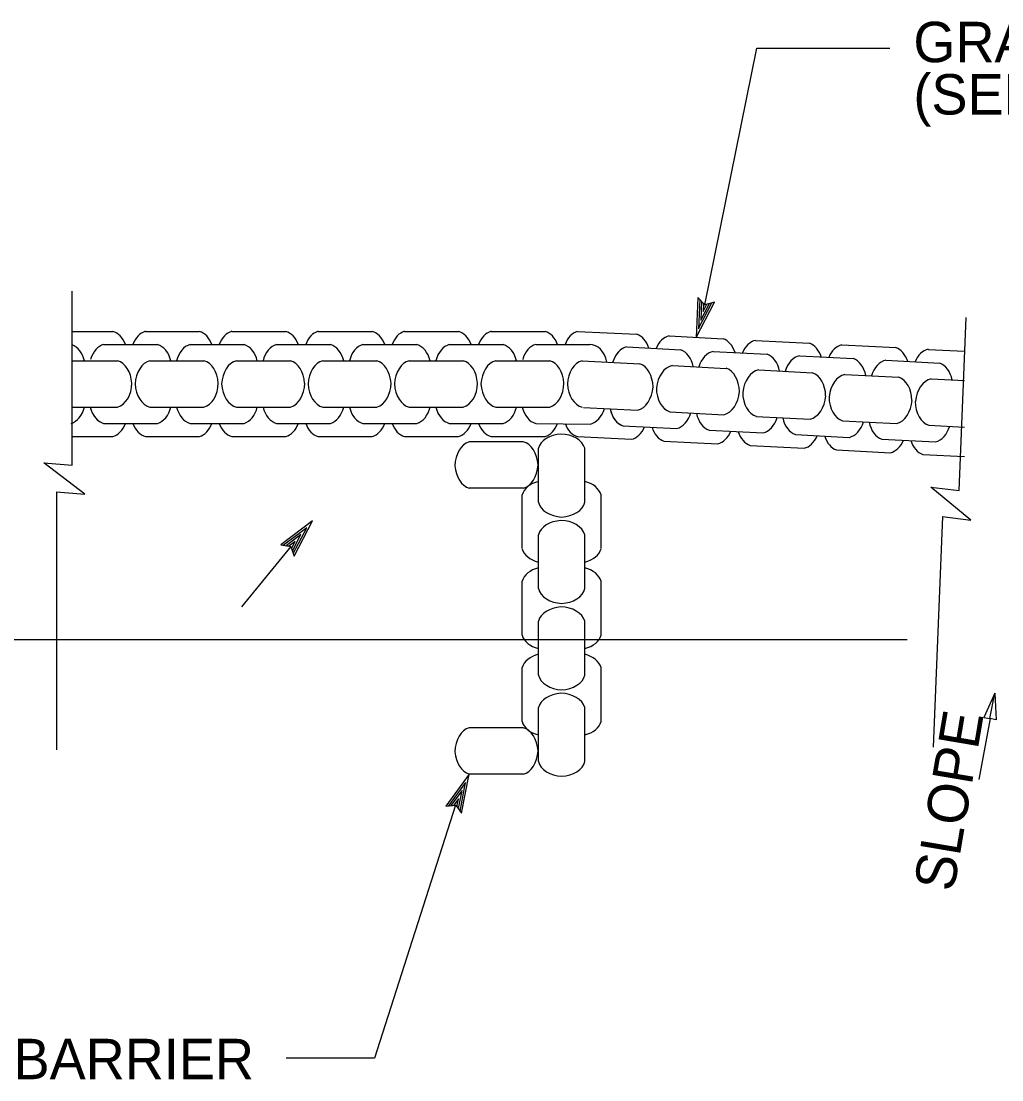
# Model space of a CAD drawing. Extents: x 6707406 to 6714471, y 1868570 to 1872341.
# Drawn here: x 6712657.6 to 6712803, y 1870285.3 to 1870442.4 of the extents above; entities that cross this region are included whole.
import ezdxf

# ---------------------------------------------------------------- set-up
doc = ezdxf.new("R2010")
doc.units = 0
for name, color, linetype in [('56 Stg 3 Anno', 7, 'Continuous'), ('C - SANDBAG', 7, 'Continuous'), ('G-SYMB', 7, 'Continuous'), ('G-TEXT', 7, 'Continuous')]:
    doc.layers.add(name, color=color, linetype=linetype)

msp = doc.modelspace()

# ---------------------------------------------------------------- linework, layer by layer
at = {"layer": '56 Stg 3 Anno'}
for p, q in [((6712757.94, 1870401.35), (6712757.69, 1870395.45)), ((6712757.69, 1870395.45), (6712760.42, 1870400.68)), ((6712758.98, 1870400.27), (6712757.94, 1870401.35)), ((6712757.94, 1870401.35), (6712757.94, 1870401.35)), ((6712758.22, 1870401.06), (6712758.03, 1870396.73)), ((6712758.04, 1870396.74), (6712760.02, 1870400.55)), ((6712758.49, 1870400.75), (6712758.37, 1870398.01)), ((6712758.37, 1870398.01), (6712759.66, 1870400.47)), ((6712758.77, 1870400.5), (6712758.72, 1870399.29)), ((6712758.72, 1870399.29), (6712759.27, 1870400.35)), ((6712760.42, 1870400.68), (6712758.98, 1870400.27)), ((6712760.42, 1870400.68), (6712760.42, 1870400.68)), ((6712757.69, 1870395.45), (6712757.69, 1870395.45)), ((6712700.78, 1870368.21), (6712696.07, 1870364.65)), ((6712699.91, 1870367.19), (6712696.48, 1870364.6)), ((6712697.9, 1870363.37), (6712699.92, 1870367.2)), ((6712698.03, 1870362.99), (6712700.78, 1870368.21)), ((6712700.78, 1870368.21), (6712700.78, 1870368.21)), ((6712699.06, 1870366.19), (6712696.85, 1870364.51)), ((6712697.78, 1870363.76), (6712699.06, 1870366.19)), ((6712696.07, 1870364.65), (6712696.07, 1870364.65)), ((6712696.07, 1870364.65), (6712697.54, 1870364.41)), ((6712698.2, 1870365.18), (6712697.26, 1870364.46)), ((6712697.54, 1870364.41), (6712698.03, 1870362.99)), ((6712697.64, 1870364.11), (6712698.2, 1870365.18)), ((6712698.03, 1870362.99), (6712698.03, 1870362.99)), ((6712724.02, 1870330.63), (6712720.53, 1870325.88)), ((6712723.48, 1870329.41), (6712720.94, 1870325.94)), ((6712722.65, 1870325.17), (6712723.49, 1870329.42)), ((6712722.88, 1870324.84), (6712724.02, 1870330.63)), ((6712724.02, 1870330.63), (6712724.02, 1870330.63)), ((6712722.95, 1870328.21), (6712721.31, 1870325.97)), ((6712722.42, 1870325.52), (6712722.95, 1870328.21)), ((6712720.53, 1870325.88), (6712722.01, 1870326.06)), ((6712722.42, 1870326.99), (6712721.72, 1870326.03)), ((6712722.01, 1870326.06), (6712722.88, 1870324.84)), ((6712722.18, 1870325.81), (6712722.42, 1870326.99)), ((6712720.53, 1870325.88), (6712720.53, 1870325.88)), ((6712722.88, 1870324.84), (6712722.88, 1870324.84))]:
    msp.add_line(p, q, dxfattribs=at)
at = {"layer": 'C - SANDBAG'}
for p, q in [((6712665.12, 1870396.34), (6712671.16, 1870396.34)), ((6712675.98, 1870396.34), (6712683.98, 1870396.34)), ((6712675.98, 1870396.34), (6712683.98, 1870396.34)), ((6712688.8, 1870396.34), (6712696.8, 1870396.34)), ((6712701.62, 1870396.34), (6712709.63, 1870396.34)), ((6712714.44, 1870396.34), (6712722.45, 1870396.34)), ((6712727.26, 1870396.34), (6712735.27, 1870396.34)), ((6712740.08, 1870396.34), (6712748.88, 1870395.9)), ((6712753.69, 1870395.66), (6712761.68, 1870395.24)), ((6712753.69, 1870395.66), (6712761.68, 1870395.24)), ((6712669.78, 1870394.39), (6712677.79, 1870394.39)), ((6712669.78, 1870394.39), (6712677.79, 1870394.39)), ((6712682.6, 1870394.39), (6712690.61, 1870394.39)), ((6712695.42, 1870394.39), (6712703.43, 1870394.39)), ((6712708.25, 1870394.39), (6712716.25, 1870394.39)), ((6712721.07, 1870394.39), (6712729.07, 1870394.39)), ((6712733.89, 1870394.38), (6712741.89, 1870394.38)), ((6712747.4, 1870394.02), (6712755.4, 1870393.61)), ((6712747.4, 1870394.02), (6712755.4, 1870393.61)), ((6712766.49, 1870394.99), (6712774.49, 1870394.58)), ((6712779.3, 1870394.33), (6712787.29, 1870393.92)), ((6712792.1, 1870393.67), (6712797.47, 1870393.4)), ((6712760.21, 1870393.36), (6712768.2, 1870392.95)), ((6712773.01, 1870392.7), (6712781.01, 1870392.29)), ((6712785.81, 1870392.04), (6712793.81, 1870391.63)), ((6712665.12, 1870391.98), (6712671.85, 1870391.98)), ((6712676.67, 1870391.98), (6712684.67, 1870391.98)), ((6712676.67, 1870391.98), (6712684.67, 1870391.98)), ((6712689.49, 1870391.98), (6712697.49, 1870391.98)), ((6712702.31, 1870391.98), (6712710.31, 1870391.98)), ((6712715.13, 1870391.98), (6712723.13, 1870391.98)), ((6712727.95, 1870391.98), (6712735.96, 1870391.98)), ((6712740.77, 1870391.98), (6712749.34, 1870391.52)), ((6712754.15, 1870391.27), (6712762.15, 1870390.85)), ((6712754.15, 1870391.27), (6712762.15, 1870390.85)), ((6712766.96, 1870390.61), (6712774.95, 1870390.19)), ((6712779.76, 1870389.95), (6712787.76, 1870389.53)), ((6712792.56, 1870389.28), (6712797.47, 1870389.03)), ((6712665.12, 1870385.09), (6712671.85, 1870385.09)), ((6712676.67, 1870385.09), (6712684.67, 1870385.09)), ((6712676.67, 1870385.09), (6712684.67, 1870385.09)), ((6712689.49, 1870385.09), (6712697.49, 1870385.09)), ((6712702.31, 1870385.09), (6712710.31, 1870385.09)), ((6712715.13, 1870385.09), (6712723.13, 1870385.09)), ((6712727.95, 1870385.09), (6712735.96, 1870385.09)), ((6712740.99, 1870385.05), (6712748.99, 1870384.63)), ((6712753.8, 1870384.39), (6712761.79, 1870383.97)), ((6712753.8, 1870384.39), (6712761.79, 1870383.97)), ((6712669.78, 1870382.68), (6712677.79, 1870382.68)), ((6712669.78, 1870382.68), (6712677.79, 1870382.68)), ((6712682.6, 1870382.68), (6712690.61, 1870382.68)), ((6712695.42, 1870382.68), (6712703.43, 1870382.68)), ((6712708.25, 1870382.68), (6712716.25, 1870382.68)), ((6712721.07, 1870382.68), (6712729.07, 1870382.68)), ((6712733.89, 1870382.68), (6712741.99, 1870382.59)), ((6712766.6, 1870383.72), (6712774.6, 1870383.31)), ((6712779.4, 1870383.06), (6712787.4, 1870382.65)), ((6712746.8, 1870382.34), (6712754.8, 1870381.92)), ((6712746.8, 1870382.34), (6712754.8, 1870381.92)), ((6712759.6, 1870381.68), (6712767.6, 1870381.26)), ((6712792.21, 1870382.4), (6712797.47, 1870382.13)), ((6712665.12, 1870380.73), (6712671.16, 1870380.73)), ((6712675.98, 1870380.73), (6712683.98, 1870380.73)), ((6712675.98, 1870380.73), (6712683.98, 1870380.73)), ((6712688.8, 1870380.73), (6712696.8, 1870380.73)), ((6712701.62, 1870380.73), (6712709.63, 1870380.73)), ((6712714.44, 1870380.73), (6712722.45, 1870380.73)), ((6712732.03, 1870379.96), (6712724.02, 1870379.96)), ((6712727.26, 1870380.73), (6712735.27, 1870380.73)), ((6712740.08, 1870380.73), (6712748.08, 1870380.32)), ((6712752.88, 1870380.07), (6712760.88, 1870379.66)), ((6712752.88, 1870380.07), (6712760.88, 1870379.66)), ((6712772.41, 1870381.01), (6712780.4, 1870380.6)), ((6712785.21, 1870380.35), (6712793.21, 1870379.94)), ((6712734.28, 1870370.98), (6712734.28, 1870378.99)), ((6712741.17, 1870370.98), (6712741.17, 1870378.99)), ((6712765.69, 1870379.41), (6712773.68, 1870378.99)), ((6712778.49, 1870378.75), (6712786.49, 1870378.33)), ((6712791.3, 1870378.08), (6712797.47, 1870377.77)), ((6712732.03, 1870373.07), (6712724.02, 1870373.07)), ((6712731.87, 1870364.1), (6712731.87, 1870372.1)), ((6712743.57, 1870364.1), (6712743.57, 1870372.1)), ((6712734.28, 1870358.16), (6712734.28, 1870366.17)), ((6712741.17, 1870358.16), (6712741.17, 1870366.17)), ((6712731.87, 1870351.28), (6712731.87, 1870359.28)), ((6712743.57, 1870351.28), (6712743.57, 1870359.28)), ((6712734.28, 1870345.34), (6712734.28, 1870353.35)), ((6712741.17, 1870345.34), (6712741.17, 1870353.35)), ((6712731.87, 1870338.46), (6712731.87, 1870346.46)), ((6712743.57, 1870338.46), (6712743.57, 1870346.46)), ((6712734.28, 1870332.52), (6712734.28, 1870340.52)), ((6712734.28, 1870332.52), (6712734.28, 1870340.52)), ((6712741.17, 1870332.52), (6712741.17, 1870340.52)), ((6712741.17, 1870332.52), (6712741.17, 1870340.52)), ((6712732.03, 1870337.53), (6712724.02, 1870337.53)), ((6712732.03, 1870330.63), (6712724.02, 1870330.63))]:
    msp.add_line(p, q, dxfattribs=at)
for centre, major_axis, ratio, start_param, end_param in [((6712670.68, 1870392.66), (0.06, -3.75), 0.71077, 2.038051, 2.935943), ((6712676.5, 1870392.66), (0.06, -3.75), 0.711359, 3.317588, 4.221159), ((6712676.5, 1870392.66), (0.06, -3.75), 0.711359, 3.317588, 4.221159), ((6712683.5, 1870392.66), (0.06, -3.75), 0.71077, 2.038051, 2.935943), ((6712683.5, 1870392.66), (0.06, -3.75), 0.71077, 2.038051, 2.935943), ((6712689.32, 1870392.66), (0.06, -3.75), 0.711359, 3.317588, 4.221159), ((6712696.32, 1870392.66), (0.06, -3.75), 0.71077, 2.038051, 2.935943), ((6712702.14, 1870392.66), (0.06, -3.75), 0.711359, 3.317588, 4.221159), ((6712709.14, 1870392.66), (0.06, -3.75), 0.71077, 2.038051, 2.935943), ((6712714.96, 1870392.66), (0.06, -3.75), 0.711359, 3.317588, 4.221159), ((6712721.96, 1870392.66), (0.06, -3.75), 0.71077, 2.038051, 2.935943), ((6712727.79, 1870392.66), (0.06, -3.75), 0.711359, 3.317588, 4.221159), ((6712734.78, 1870392.66), (0.06, -3.75), 0.71077, 2.038051, 2.935943), ((6712740.61, 1870392.65), (0.06, -3.75), 0.711359, 3.317588, 4.221159), ((6712748.21, 1870392.25), (-0.13, -3.75), 0.71077, 2.038051, 2.935943), ((6712754.02, 1870391.95), (-0.13, -3.75), 0.711359, 3.317588, 4.221159), ((6712754.02, 1870391.95), (-0.13, -3.75), 0.711359, 3.317588, 4.221159), ((6712761.01, 1870391.59), (-0.13, -3.75), 0.71077, 2.038051, 2.935943), ((6712761.01, 1870391.59), (-0.13, -3.75), 0.71077, 2.038051, 2.935943), ((6712664.43, 1870390.71), (0, -3.75), 0.71077, 1.915159, 2.876513), ((6712670.31, 1870390.7), (0.06, -3.75), 0.711359, 3.317588, 4.29466), ((6712670.31, 1870390.7), (0.06, -3.75), 0.711359, 3.317588, 4.29466), ((6712677.25, 1870390.71), (0, -3.75), 0.71077, 1.915159, 2.935943), ((6712677.25, 1870390.71), (0, -3.75), 0.71077, 1.915159, 2.935943), ((6712683.13, 1870390.7), (0.06, -3.75), 0.711359, 3.317588, 4.353284), ((6712690.07, 1870390.71), (0, -3.75), 0.71077, 1.915159, 2.935943), ((6712695.95, 1870390.7), (0.06, -3.75), 0.711359, 3.317588, 4.353284), ((6712702.89, 1870390.71), (0, -3.75), 0.71077, 1.915159, 2.935943), ((6712708.77, 1870390.7), (0.06, -3.75), 0.711359, 3.317588, 4.353284), ((6712715.71, 1870390.71), (0, -3.75), 0.71077, 1.915159, 2.935943), ((6712721.59, 1870390.7), (0.06, -3.75), 0.711359, 3.317588, 4.353284), ((6712728.53, 1870390.71), (0, -3.75), 0.71077, 1.915159, 2.935943), ((6712734.41, 1870390.7), (0.06, -3.75), 0.711359, 3.317588, 4.29466), ((6712741.86, 1870390.63), (-0.19, -3.75), 0.71077, 1.915159, 3.202147), ((6712747.74, 1870390.32), (-0.13, -3.75), 0.711359, 3.317588, 4.350526), ((6712747.74, 1870390.32), (-0.13, -3.75), 0.711359, 3.317588, 4.29466), ((6712754.67, 1870389.97), (-0.19, -3.75), 0.71077, 1.915159, 2.935943), ((6712754.67, 1870389.97), (-0.19, -3.75), 0.71077, 1.915159, 2.935943), ((6712766.83, 1870391.29), (-0.13, -3.75), 0.711359, 3.317588, 4.221159), ((6712773.81, 1870390.93), (-0.13, -3.75), 0.71077, 2.038051, 2.935943), ((6712779.63, 1870390.63), (-0.13, -3.75), 0.711359, 3.317588, 4.221159), ((6712786.62, 1870390.27), (-0.13, -3.75), 0.71077, 2.038051, 2.935943), ((6712792.44, 1870389.97), (-0.13, -3.75), 0.711359, 3.317588, 4.221159), ((6712760.54, 1870389.66), (-0.13, -3.75), 0.711359, 3.317588, 4.353284), ((6712767.47, 1870389.31), (-0.19, -3.75), 0.71077, 1.915159, 2.935943), ((6712773.35, 1870389), (-0.13, -3.75), 0.711359, 3.317588, 4.353284), ((6712780.27, 1870388.65), (-0.19, -3.75), 0.71077, 1.915159, 2.935943), ((6712786.15, 1870388.34), (-0.13, -3.75), 0.711359, 3.317588, 4.353284), ((6712671.31, 1870388.31), (0, -3.75), 0.71077, 1.662213, 2.935943), ((6712677.13, 1870388.29), (0, -3.75), 0.711359, 3.317588, 4.646994), ((6712677.13, 1870388.29), (0, -3.75), 0.711359, 3.317588, 4.646994), ((6712684.13, 1870388.31), (0, -3.75), 0.71077, 1.662213, 2.935943), ((6712684.13, 1870388.31), (0, -3.75), 0.71077, 1.662213, 2.935943), ((6712689.95, 1870388.29), (0, -3.75), 0.711359, 3.317588, 4.646994), ((6712696.95, 1870388.31), (0, -3.75), 0.71077, 1.662213, 2.935943), ((6712702.77, 1870388.29), (0, -3.75), 0.711359, 3.317588, 4.646994), ((6712709.77, 1870388.31), (0, -3.75), 0.71077, 1.662213, 2.935943), ((6712715.59, 1870388.29), (0, -3.75), 0.711359, 3.317588, 4.646994), ((6712722.59, 1870388.31), (0, -3.75), 0.71077, 1.662213, 2.935943), ((6712728.42, 1870388.29), (0, -3.75), 0.711359, 3.317588, 4.646994), ((6712735.41, 1870388.31), (0, -3.75), 0.71077, 1.662213, 2.935943), ((6712741.24, 1870388.29), (0, -3.75), 0.711359, 3.317588, 4.646994), ((6712748.61, 1870387.88), (-0.19, -3.75), 0.71077, 1.662213, 2.935943), ((6712754.43, 1870387.56), (-0.19, -3.74), 0.711359, 3.317588, 4.646994), ((6712754.43, 1870387.56), (-0.19, -3.74), 0.711359, 3.317588, 4.646994), ((6712761.42, 1870387.22), (-0.19, -3.75), 0.71077, 1.662213, 2.935943), ((6712761.42, 1870387.22), (-0.19, -3.75), 0.71077, 1.662213, 2.935943), ((6712767.23, 1870386.9), (-0.19, -3.74), 0.711359, 3.317588, 4.646994), ((6712793.08, 1870387.99), (-0.19, -3.75), 0.71077, 1.915159, 2.935943), ((6712774.22, 1870386.55), (-0.19, -3.75), 0.71077, 1.662213, 2.935943), ((6712780.04, 1870386.24), (-0.19, -3.74), 0.711359, 3.317588, 4.646994), ((6712787.02, 1870385.89), (-0.19, -3.75), 0.71077, 1.662213, 2.935943), ((6712792.84, 1870385.57), (-0.19, -3.74), 0.711359, 3.317588, 4.646994), ((6712671.31, 1870388.76), (0, 3.75), 0.71077, 3.347242, 4.682592), ((6712677.13, 1870388.78), (0, 3.75), 0.711359, 1.636191, 2.965597), ((6712677.13, 1870388.78), (0, 3.75), 0.711359, 1.636191, 2.965597), ((6712684.13, 1870388.76), (0, 3.75), 0.71077, 3.347242, 4.682592), ((6712684.13, 1870388.76), (0, 3.75), 0.71077, 3.347242, 4.682592), ((6712689.95, 1870388.78), (0, 3.75), 0.711359, 1.636191, 2.965597), ((6712696.95, 1870388.76), (0, 3.75), 0.71077, 3.347242, 4.682592), ((6712702.77, 1870388.78), (0, 3.75), 0.711359, 1.636191, 2.965597), ((6712709.77, 1870388.76), (0, 3.75), 0.71077, 3.347242, 4.682592), ((6712715.59, 1870388.78), (0, 3.75), 0.711359, 1.636191, 2.965597), ((6712722.59, 1870388.76), (0, 3.75), 0.71077, 3.347242, 4.682592), ((6712728.42, 1870388.78), (0, 3.75), 0.711359, 1.636191, 2.965597), ((6712735.41, 1870388.76), (0, 3.75), 0.71077, 3.347242, 4.682592), ((6712741.24, 1870388.78), (0, 3.75), 0.711359, 1.636191, 2.965597), ((6712748.63, 1870388.33), (0.19, 3.75), 0.71077, 3.347242, 4.682592), ((6712754.45, 1870388.05), (0.19, 3.74), 0.711359, 1.636191, 2.965597), ((6712754.45, 1870388.05), (0.19, 3.74), 0.711359, 1.636191, 2.965597), ((6712761.44, 1870387.67), (0.19, 3.75), 0.71077, 3.347242, 4.682592), ((6712761.44, 1870387.67), (0.19, 3.75), 0.71077, 3.347242, 4.682592), ((6712767.26, 1870387.39), (0.19, 3.74), 0.711359, 1.636191, 2.965597), ((6712774.24, 1870387.01), (0.19, 3.75), 0.71077, 3.347242, 4.682592), ((6712780.06, 1870386.72), (0.19, 3.74), 0.711359, 1.636191, 2.965597), ((6712787.05, 1870386.35), (0.19, 3.75), 0.71077, 3.347242, 4.682592), ((6712792.86, 1870386.06), (0.19, 3.74), 0.711359, 1.636191, 2.965597), ((6712664.43, 1870386.36), (0, 3.75), 0.71077, 3.347242, 4.368026), ((6712670.31, 1870386.37), (0.06, 3.75), 0.711359, 1.929645, 2.965597), ((6712670.31, 1870386.37), (0.06, 3.75), 0.711359, 1.988526, 2.965597), ((6712677.25, 1870386.36), (0, 3.75), 0.71077, 3.347242, 4.368026), ((6712677.25, 1870386.36), (0, 3.75), 0.71077, 3.347242, 4.368026), ((6712683.13, 1870386.37), (0.06, 3.75), 0.711359, 1.929645, 2.965597), ((6712690.07, 1870386.36), (0, 3.75), 0.71077, 3.347242, 4.368026), ((6712695.95, 1870386.37), (0.06, 3.75), 0.711359, 1.929645, 2.965597), ((6712702.89, 1870386.36), (0, 3.75), 0.71077, 3.347242, 4.368026), ((6712708.77, 1870386.36), (0.06, 3.75), 0.711359, 1.929645, 2.965597), ((6712715.71, 1870386.35), (0, 3.75), 0.71077, 3.347242, 4.368026), ((6712721.59, 1870386.36), (0.06, 3.75), 0.711359, 1.929645, 2.965597), ((6712728.53, 1870386.35), (0, 3.75), 0.71077, 3.347242, 4.368026), ((6712734.41, 1870386.36), (0.06, 3.75), 0.711359, 1.929645, 2.965597), ((6712741.64, 1870386.28), (0.19, 3.75), 0.71077, 3.347242, 4.368026), ((6712747.51, 1870385.99), (0.25, 3.74), 0.711359, 1.929645, 2.965597), ((6712747.51, 1870385.99), (0.25, 3.74), 0.711359, 1.988526, 2.965597), ((6712754.44, 1870385.62), (0.19, 3.75), 0.71077, 3.347242, 4.368026), ((6712754.44, 1870385.62), (0.19, 3.75), 0.71077, 3.347242, 4.368026), ((6712760.32, 1870385.33), (0.25, 3.74), 0.711359, 1.929645, 2.965597), ((6712670.68, 1870384.41), (0.06, 3.75), 0.71077, 3.347242, 4.244863), ((6712676.5, 1870384.41), (0.06, 3.75), 0.711359, 2.062027, 2.965597), ((6712676.5, 1870384.41), (0.06, 3.75), 0.711359, 2.062027, 2.965597), ((6712683.5, 1870384.41), (0.06, 3.75), 0.71077, 3.347242, 4.244863), ((6712683.5, 1870384.41), (0.06, 3.75), 0.71077, 3.347242, 4.244863), ((6712689.32, 1870384.41), (0.06, 3.75), 0.711359, 2.062027, 2.965597), ((6712696.32, 1870384.41), (0.06, 3.75), 0.71077, 3.347242, 4.244863), ((6712702.14, 1870384.41), (0.06, 3.75), 0.711359, 2.062027, 2.965597), ((6712709.14, 1870384.41), (0.06, 3.75), 0.71077, 3.347242, 4.244863), ((6712714.96, 1870384.41), (0.06, 3.75), 0.711359, 2.062027, 2.965597), ((6712721.96, 1870384.41), (0.06, 3.75), 0.71077, 3.347242, 4.244863), ((6712727.79, 1870384.41), (0.06, 3.75), 0.711359, 2.062027, 2.965597), ((6712734.78, 1870384.41), (0.06, 3.75), 0.71077, 3.347242, 4.244863), ((6712740.61, 1870384.41), (0.06, 3.75), 0.711359, 2.062027, 2.965597), ((6712767.25, 1870384.96), (0.19, 3.75), 0.71077, 3.347242, 4.368026), ((6712773.12, 1870384.67), (0.25, 3.74), 0.711359, 1.929645, 2.965597), ((6712780.05, 1870384.3), (0.19, 3.75), 0.71077, 3.347242, 4.368026), ((6712785.93, 1870384), (0.25, 3.74), 0.711359, 1.929645, 2.965597), ((6712737.95, 1870378.44), (3.75, 0), 0.71077, 1.662213, 2.935943), ((6712737.5, 1870378.44), (-3.75, 0), 0.71077, 3.347242, 4.682592), ((6712747.78, 1870384.02), (0.25, 3.74), 0.71077, 3.347242, 4.244863), ((6712753.6, 1870383.72), (0.25, 3.74), 0.711359, 2.062027, 2.965597), ((6712753.6, 1870383.72), (0.25, 3.74), 0.711359, 2.062027, 2.965597), ((6712760.59, 1870383.36), (0.25, 3.74), 0.71077, 3.347242, 4.244863), ((6712760.59, 1870383.36), (0.25, 3.74), 0.71077, 3.347242, 4.244863), ((6712766.4, 1870383.06), (0.25, 3.74), 0.711359, 2.062027, 2.965597), ((6712792.85, 1870383.64), (0.19, 3.75), 0.71077, 3.347242, 4.368026), ((6712724.56, 1870376.28), (0, -3.75), 0.71077, 3.347242, 4.682592), ((6712731.56, 1870376.27), (0, -3.75), 0.711359, 1.636191, 2.965597), ((6712773.39, 1870382.7), (0.25, 3.74), 0.71077, 3.347242, 4.244863), ((6712779.21, 1870382.4), (0.25, 3.74), 0.711359, 2.062027, 2.965597), ((6712786.19, 1870382.03), (0.25, 3.74), 0.71077, 3.347242, 4.244863), ((6712792.01, 1870381.74), (0.25, 3.74), 0.711359, 2.062027, 2.965597), ((6712724.56, 1870376.74), (0, 3.75), 0.71077, 1.662213, 2.935943), ((6712731.56, 1870376.76), (0, 3.75), 0.711359, 3.317588, 4.646994), ((6712735.54, 1870371.56), (3.75, 0), 0.71077, 1.915159, 2.935943), ((6712739.9, 1870371.56), (-3.75, 0), 0.71077, 3.347242, 4.368026), ((6712737.97, 1870371.45), (3.75, 0), 0.711359, 3.317588, 4.646994), ((6712737.48, 1870371.45), (-3.75, 0), 0.711359, 1.636191, 2.965597), ((6712737.95, 1870365.62), (3.75, 0), 0.71077, 1.662213, 2.935943), ((6712737.49, 1870365.62), (-3.75, 0), 0.71077, 3.347242, 4.682592), ((6712735.55, 1870364.62), (3.75, 0.06), 0.711359, 3.317588, 4.353284), ((6712739.89, 1870364.62), (-3.75, 0.06), 0.711359, 1.929645, 2.965597), ((6712735.54, 1870358.74), (3.75, 0), 0.71077, 1.915159, 2.935943), ((6712739.9, 1870358.74), (-3.75, 0), 0.71077, 3.347242, 4.368026), ((6712737.97, 1870358.63), (3.75, 0), 0.711359, 3.317588, 4.646994), ((6712737.48, 1870358.63), (-3.75, 0), 0.711359, 1.636191, 2.965597), ((6712737.95, 1870352.8), (3.75, 0), 0.71077, 1.662213, 2.935943), ((6712737.49, 1870352.8), (-3.75, 0), 0.71077, 3.347242, 4.682592), ((6712735.55, 1870351.8), (3.75, 0.06), 0.711359, 3.317588, 4.353284), ((6712739.89, 1870351.8), (-3.75, 0.06), 0.711359, 1.929645, 2.965597), ((6712735.54, 1870345.92), (3.75, 0), 0.71077, 1.915159, 2.935943), ((6712739.9, 1870345.92), (-3.75, 0), 0.71077, 3.347242, 4.368026), ((6712737.97, 1870345.81), (3.75, 0), 0.711359, 3.317588, 4.646994), ((6712737.48, 1870345.81), (-3.75, 0), 0.711359, 1.636191, 2.965597), ((6712737.95, 1870339.98), (3.75, 0), 0.71077, 1.662213, 2.935943), ((6712737.95, 1870339.98), (3.75, 0), 0.71077, 1.662213, 2.935943), ((6712737.49, 1870339.98), (-3.75, 0), 0.71077, 3.347242, 4.682592), ((6712737.49, 1870339.98), (-3.75, 0), 0.71077, 3.347242, 4.682592), ((6712724.56, 1870333.85), (0, -3.75), 0.71077, 3.347242, 4.682592), ((6712735.55, 1870338.98), (3.75, 0.06), 0.711359, 3.317588, 4.353284), ((6712731.56, 1870333.83), (0, -3.75), 0.711359, 1.636191, 2.965597), ((6712739.89, 1870338.98), (-3.75, 0.06), 0.711359, 1.929645, 2.965597), ((6712724.56, 1870334.31), (0, 3.75), 0.71077, 1.662213, 2.935943), ((6712731.56, 1870334.32), (0, 3.75), 0.711359, 3.317588, 4.646994), ((6712737.97, 1870332.98), (3.75, 0), 0.711359, 3.317588, 4.646994), ((6712737.48, 1870332.98), (-3.75, 0), 0.711359, 1.636191, 2.965597)]:
    msp.add_ellipse(centre, major_axis=major_axis, ratio=ratio, start_param=start_param, end_param=end_param, dxfattribs=at)
at = {"layer": 'G-SYMB'}
for p, q in [((6712665.12, 1870376.49), (6712665.12, 1870402.29)), ((6712796.69, 1870372.71), (6712797.74, 1870398.39)), ((6712665.12, 1870376.49), (6712665.12, 1870376.49)), ((6712662.81, 1870372.55), (6712662.81, 1870372.55)), ((6712662.81, 1870372.55), (6712662.81, 1870334.23)), ((6712796.69, 1870372.71), (6712796.69, 1870372.71)), ((6712794.22, 1870368.87), (6712792.82, 1870334.64)), ((6712794.22, 1870368.87), (6712794.22, 1870368.87)), ((6712697.56, 1870364.41), (6712690.22, 1870355.44)), ((6712401.02, 1870350.62), (6712788.96, 1870350.62)), ((6712801.28, 1870338.9), (6712799.62, 1870329.86)), ((6712801.28, 1870338.9), (6712799.62, 1870329.86))]:
    msp.add_line(p, q, dxfattribs=at)
for points in [[(6712662.81, 1870372.55), (6712667.02, 1870372.19), (6712660.91, 1870376.84), (6712665.12, 1870376.49)], [(6712794.22, 1870368.87), (6712798.42, 1870368.34), (6712792.5, 1870373.24), (6712796.69, 1870372.71)]]:
    msp.add_lwpolyline(points, dxfattribs=at)
for points in [[(6712663.96, 1870374.52), (6712663.96, 1870374.52)], [(6712795.46, 1870370.79), (6712795.46, 1870370.79)], [(6712800.38, 1870339.04), (6712801.27, 1870338.88), (6712801.97, 1870342.67)], [(6712802.17, 1870338.71), (6712801.27, 1870338.88), (6712801.97, 1870342.67)]]:
    msp.add_lwpolyline(points, close=True, dxfattribs=at)
at = {"layer": 'G-TEXT'}
for p, q in [((6712758.98, 1870400.27), (6712766.67, 1870438.35)), ((6712766.67, 1870438.35), (6712786.4, 1870438.35)), ((6712721.99, 1870326.05), (6712709.95, 1870288.5)), ((6712709.95, 1870288.5), (6712696.85, 1870288.5))]:
    msp.add_line(p, q, dxfattribs=at)

# ---------------------------------------------------------------- texts
for s, rotation, p in [('GRAVEL BAG BERM', 360, (6712789.91, 1870436.27)), ('(SEE NOTE 4)', 360, (6712789.91, 1870428.51)), ('SLOPE', 80.3882, (6712795.87, 1870313.05)), ('CROSS BARRIER', 360, (6712625.66, 1870285.37))]:
    msp.add_text(s, height=6, rotation=rotation, dxfattribs=at).set_placement(p)

doc.saveas('drawing.dxf')
